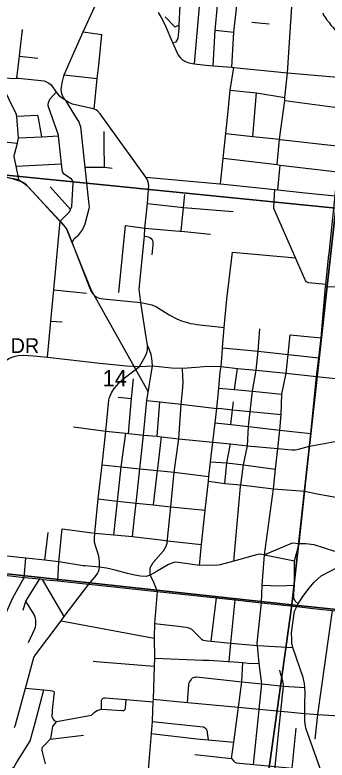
# Model space of a CAD drawing. Extents: x -8.2 to 38.5, y -0.1 to 21.9.
# Drawn here: x 6.953 to 7.75, y 15.475 to 17.376 of the extents above; entities that cross this region are included whole.
import ezdxf

# ---------------------------------------------------------------- set-up
doc = ezdxf.new("R2010")
doc.units = 0
for name, color, linetype in [('GM_X_Adjacent_County_Text', 7, 'Continuous'), ('GM_X_Airport_Location_Class_3', 7, 'Continuous'), ('GM_X_County_Road_Text', 7, 'Continuous'), ('GM_X_Major_Lake', 7, 'Continuous'), ('GM_X_Minor_River', 7, 'Continuous'), ('GM_X_Township_Subdivision_Text', 7, 'Continuous'), ('GM_X_Township_Text', 7, 'Continuous'), ('GM_X_US_Location', 7, 'Continuous')]:
    doc.layers.add(name, color=color, linetype=linetype)

msp = doc.modelspace()

# ---------------------------------------------------------------- linework, layer by layer
at = {"layer": 'GM_X_Adjacent_County_Text'}
for points in [[(6.8589, 17.9964), (7.8777, 17.8803), (7.7722, 16.8835), (6.7536, 16.9855)], [(6.7536, 16.9855), (7.7722, 16.8835), (7.66, 15.8712), (6.65, 15.9814)], [(7.7722, 16.8835), (8.7794, 16.8117), (8.6736, 15.7659), (7.66, 15.8712)], [(7.66, 15.8712), (7.5202, 14.8634), (6.5306, 14.9717), (6.65, 15.9814)], [(7.66, 15.8712), (8.6736, 15.7659), (8.6117, 15.0774), (8.5928, 15.0619), (8.5723, 15.0415), (8.5525, 15.0184), (8.5405, 15.0046), (8.5226, 14.9831), (8.5094, 14.9667), (8.4937, 14.9454), (8.4864, 14.9373), (8.469, 14.9221), (8.4519, 14.9028), (8.4387, 14.8852), (8.4261, 14.8666), (8.4156, 14.8524), (8.4049, 14.847), (8.3954, 14.8305), (8.3869, 14.8201), (8.3765, 14.8112), (8.3645, 14.8016), (8.3536, 14.7875), (8.3469, 14.777), (7.5202, 14.8634)]]:
    msp.add_lwpolyline(points, close=True, dxfattribs=at)
at = {"layer": 'GM_X_Airport_Location_Class_3'}
msp.add_line((7.6679, 15.8566), (7.6718, 15.8654), dxfattribs=at)
for points in [[(7.6718, 15.8654), (7.6726, 15.8672), (7.6765, 15.8737), (7.6884, 15.8923), (7.7048, 15.9142), (7.717, 15.929), (7.7347, 15.9451), (7.7619, 15.959), (7.7744, 15.9656), (7.7953, 15.9816), (7.8059, 15.9913)], [(7.6628, 15.7625), (7.6606, 15.7735), (7.6599, 15.7828), (7.6597, 15.7997), (7.6672, 15.8548), (7.6679, 15.8566)], [(7.7413, 15.3282), (7.7488, 15.38), (7.7503, 15.3899), (7.749, 15.4031), (7.7461, 15.4159), (7.7314, 15.4563), (7.6959, 15.5563), (7.6932, 15.5748), (7.6932, 15.5939), (7.693, 15.6174), (7.6947, 15.648), (7.6938, 15.6606), (7.6922, 15.671), (7.6889, 15.6856), (7.6628, 15.7625)]]:
    msp.add_lwpolyline(points, dxfattribs=at)
at = {"layer": 'GM_X_Minor_River'}
msp.add_lwpolyline([(7.7395, 17.3818), (7.7413, 17.376), (7.746, 17.369), (7.7486, 17.3647), (7.7556, 17.3573), (7.7596, 17.3503), (7.7651, 17.3452), (7.7685, 17.341), (7.7743, 17.3324), (7.779, 17.3235), (7.78, 17.3193)], dxfattribs=at)
at = {"layer": 'GM_X_Township_Subdivision_Text'}
for p, q in [((7.4118, 17.2515), (7.4245, 17.3982)), ((7.5578, 17.3578), (7.6021, 17.354)), ((7.1279, 17.3332), (7.1755, 17.3266)), ((7.4644, 17.3371), (7.5122, 17.3324)), ((6.9648, 17.2708), (7.0116, 17.2657)), ((7.0794, 17.2237), (7.1636, 17.2141)), ((7.5611, 17.0665), (7.5702, 17.1774)), ((7.6426, 17.1581), (7.7987, 17.1368)), ((6.7638, 17.0677), (6.9596, 17.0492)), ((6.9563, 16.9902), (7.0723, 16.9961)), ((7.6242, 16.9301), (7.6305, 16.9934)), ((7.0956, 16.8798), (7.0431, 16.9377)), ((7.2186, 16.6683), (7.2354, 16.8388)), ((7.5085, 16.771), (7.67, 16.7563)), ((7.0526, 16.6751), (7.1359, 16.6664)), ((7.7463, 16.6839), (7.7732, 16.6831)), ((7.0448, 16.5955), (7.0742, 16.5938)), ((7.5135, 16.4207), (7.5213, 16.4747)), ((7.2169, 16.4009), (7.2514, 16.3977)), ((7.3165, 16.3013), (7.3235, 16.3894)), ((7.1026, 16.3255), (7.1853, 16.3144)), ((7.0742, 16.0653), (7.1571, 16.0546)), ((7.0298, 15.985), (7.0382, 16.0559)), ((7.5906, 15.9988), (7.6674, 15.9837)), ((7.0792, 15.8412), (7.024, 15.9364)), ((7.4544, 15.7783), (7.4679, 15.889)), ((7.0715, 15.8305), (7.3091, 15.7865)), ((7.236, 15.6075), (7.2372, 15.6298)), ((7.0599, 15.5734), (7.1485, 15.5901)), ((7.6609, 15.455), (7.6713, 15.5569)), ((7.0435, 15.5286), (7.1285, 15.5389))]:
    msp.add_line(p, q, dxfattribs=at)
for points in [[(7.6225, 16.9944), (7.6285, 17.059), (7.6426, 17.1581), (7.6428, 17.1655), (7.6492, 17.2288), (7.6623, 17.424), (7.664, 17.4416), (7.6611, 17.4592), (7.6556, 17.4742), (7.6502, 17.482), (7.6447, 17.489)], [(7.3554, 17.3064), (7.3653, 17.3077), (7.3697, 17.3166), (7.3724, 17.3418), (7.3728, 17.3502), (7.3763, 17.4185), (7.375, 17.4257), (7.3717, 17.4316), (7.3682, 17.4359), (7.3641, 17.4398), (7.3445, 17.4538)], [(7.5072, 17.2431), (7.5122, 17.3324), (7.5238, 17.4387)], [(7.4598, 17.2467), (7.4644, 17.3371), (7.4701, 17.4004)], [(7.3365, 17.3712), (7.3617, 17.3462), (7.3728, 17.3502)], [(6.9583, 17.2147), (6.9648, 17.2708), (6.9728, 17.3389)], [(7.156, 17.136), (7.1636, 17.2141), (7.1677, 17.2482), (7.1755, 17.3266)], [(7.4778, 16.9455), (7.4847, 17.0106), (7.4915, 17.0742), (7.4976, 17.1307), (7.5025, 17.1844), (7.5124, 17.2423)], [(6.7772, 17.1965), (6.8296, 17.2196), (6.8539, 17.2221), (6.9085, 17.2178), (6.9103, 17.2176), (6.9486, 17.2138), (6.9583, 17.2147), (6.9623, 17.215), (7.0281, 17.2079), (7.0373, 17.2043), (7.0404, 17.2021), (7.0458, 17.198), (7.0585, 17.1796), (7.0667, 17.1701), (7.0809, 17.1604)], [(6.9639, 16.9533), (6.9563, 16.9902), (6.9516, 17.0152), (6.9513, 17.0174), (6.9529, 17.0238), (6.9596, 17.0492), (6.9629, 17.0616), (6.9628, 17.0624), (6.9582, 17.1174), (6.9578, 17.1213), (6.957, 17.1239), (6.938, 17.1621), (6.9103, 17.2176)], [(7.0362, 16.5036), (7.0448, 16.5955), (7.0526, 16.6751), (7.0687, 16.8502), (7.0921, 16.8729), (7.0952, 16.8789), (7.0956, 16.8798), (7.0985, 16.8876), (7.1022, 16.9482), (7.1015, 16.9532), (7.0982, 16.9574), (7.0791, 16.9704), (7.0758, 16.9743), (7.0737, 16.9819), (7.0723, 16.9961), (7.0649, 17.0682), (7.0647, 17.0695), (7.0391, 17.1418), (7.0385, 17.1444), (7.0385, 17.1478), (7.0393, 17.1521), (7.0426, 17.1611), (7.0585, 17.1796)], [(7.5025, 17.1844), (7.5702, 17.1774), (7.6428, 17.1655)], [(7.0992, 16.7953), (7.1046, 16.8058), (7.1158, 16.8146), (7.1263, 16.8284), (7.1327, 16.8435), (7.1433, 16.8829), (7.1437, 16.8857), (7.1437, 16.8888), (7.1433, 16.8918), (7.1327, 16.9882), (7.1214, 17.091), (7.1185, 17.0997), (7.117, 17.1036), (7.1135, 17.1097), (7.0832, 17.1582)], [(7.0222, 17.0658), (7.0129, 17.1178), (7.0127, 17.1184), (7.012, 17.119), (7.0107, 17.1194), (6.9582, 17.1174)], [(7.1801, 17.0789), (7.1807, 17.0459), (7.1816, 16.9882)], [(7.4915, 17.0742), (7.5611, 17.0665), (7.6285, 17.059), (7.6305, 17.0588), (7.7825, 17.0418)], [(6.9628, 17.0624), (7.0222, 17.0658), (7.0649, 17.0682)], [(7.4847, 17.0106), (7.6225, 16.9944), (7.6305, 16.9934), (7.7766, 16.9762)], [(7.1327, 16.9882), (7.1698, 16.9884), (7.1816, 16.9882), (7.1831, 16.9881), (7.202, 16.9858)], [(7.7468, 16.6888), (7.7024, 16.6932), (7.6996, 16.6942), (7.6976, 16.6957), (7.6954, 16.6987), (7.6937, 16.7023), (7.67, 16.7563), (7.6145, 16.8826), (7.6139, 16.886), (7.6171, 16.9308)], [(7.3778, 16.8244), (7.384, 16.885), (7.3873, 16.9182)], [(7.2916, 16.8955), (7.384, 16.885), (7.5109, 16.875)], [(7.2354, 16.8388), (7.2854, 16.8324), (7.3737, 16.8248), (7.3778, 16.8244), (7.4527, 16.8167)], [(7.2839, 16.8118), (7.2898, 16.8108), (7.2938, 16.8099), (7.298, 16.8082), (7.3012, 16.8061), (7.3039, 16.8028), (7.3053, 16.799), (7.3058, 16.7949), (7.3051, 16.7895), (7.303, 16.764)], [(7.4872, 16.5786), (7.494, 16.6514), (7.5085, 16.771)], [(7.5126, 15.9832), (7.5295, 16.1731), (7.5301, 16.1771), (7.5372, 16.2284), (7.5475, 16.2771), (7.5496, 16.3267), (7.5538, 16.3642), (7.5596, 16.4161), (7.5693, 16.4697), (7.574, 16.5184), (7.5786, 16.5755)], [(7.2539, 16.0457), (7.259, 16.0939), (7.2628, 16.1307), (7.2721, 16.2185), (7.2818, 16.3046), (7.2904, 16.393), (7.3045, 16.4809), (7.3038, 16.4918), (7.3027, 16.5), (7.3009, 16.5104), (7.2982, 16.5194), (7.2921, 16.5335)], [(7.4835, 16.5269), (7.574, 16.5184), (7.613, 16.5142), (7.6509, 16.51), (7.7293, 16.5014)], [(7.3429, 16.0349), (7.3433, 16.0388), (7.3511, 16.1214), (7.3595, 16.2099), (7.3716, 16.2953), (7.3775, 16.3834), (7.3822, 16.4249), (7.3825, 16.4409), (7.3817, 16.453), (7.3809, 16.4748)], [(7.243, 16.3083), (7.2514, 16.3977), (7.2565, 16.448)], [(7.4736, 16.424), (7.5135, 16.4207), (7.5596, 16.4161), (7.6345, 16.4087)], [(7.2904, 16.393), (7.3235, 16.3894), (7.3775, 16.3834), (7.4684, 16.3721), (7.4736, 16.373), (7.5088, 16.369), (7.5538, 16.3642), (7.6331, 16.3569)], [(7.5044, 16.3312), (7.5088, 16.369), (7.5113, 16.3893)], [(7.4643, 16.3353), (7.5044, 16.3312), (7.5496, 16.3267), (7.6299, 16.3173), (7.7084, 16.3088)], [(7.206, 16.0498), (7.215, 16.1361), (7.225, 16.2236), (7.2361, 16.3091)], [(7.3069, 16.1261), (7.3177, 16.214), (7.3184, 16.2196), (7.3275, 16.3004)], [(7.4888, 16.1812), (7.494, 16.2335), (7.5041, 16.2819)], [(7.1757, 16.2287), (7.225, 16.2236), (7.2721, 16.2185)], [(7.2721, 16.2185), (7.3177, 16.214), (7.3595, 16.2099), (7.4486, 16.1985)], [(7.4529, 16.2361), (7.494, 16.2335), (7.5372, 16.2284), (7.6182, 16.2178)], [(7.4477, 16.1873), (7.4888, 16.1812), (7.5301, 16.1771), (7.6131, 16.1669), (7.6931, 16.161), (7.7251, 16.1549), (7.7488, 16.1499), (7.7722, 16.1461), (7.8703, 16.1164), (7.9115, 16.0891), (7.9191, 16.0839), (7.9294, 16.0789), (7.9474, 16.073), (7.9656, 16.0684), (7.9859, 16.0673), (7.996, 16.0662), (8.012, 16.0644), (8.0197, 16.0635), (8.048, 16.0596), (8.0494, 16.0595), (8.1227, 16.0521), (8.1856, 16.0457)], [(7.166, 16.1414), (7.215, 16.1361), (7.2628, 16.1307)], [(7.2628, 16.1307), (7.3069, 16.1261), (7.3511, 16.1214), (7.4392, 16.1125)], [(7.0626, 15.9327), (7.0659, 15.981), (7.0742, 16.0653)], [(7.2989, 15.9471), (7.2984, 15.9655), (7.3063, 15.9793), (7.3327, 16.0095), (7.3391, 16.0207), (7.3423, 16.0286), (7.3429, 16.0349)], [(6.8, 15.5008), (6.7852, 15.5189), (6.7836, 15.523), (6.7831, 15.5266), (6.785, 15.544), (6.7908, 15.5767), (6.7938, 15.5936), (6.7961, 15.6067), (6.798, 15.6113), (6.8006, 15.6159), (6.8205, 15.6454), (6.833, 15.6641), (6.8634, 15.7094), (6.8708, 15.7204), (6.8795, 15.7362), (6.9478, 15.8895), (6.9768, 15.9415), (6.9811, 15.9903)], [(6.9742, 15.858), (6.981, 15.8807), (7.0169, 15.9374)], [(7.5841, 15.9215), (7.627, 15.9202), (7.6667, 15.9216)], [(6.9877, 15.775), (7.0044, 15.8101), (7.006, 15.814), (7.0071, 15.8208), (7.0071, 15.8266), (7.0065, 15.8329), (7.0048, 15.8396), (7.0033, 15.8446), (7.0011, 15.8493), (6.981, 15.8807)], [(7.4999, 15.7266), (7.5046, 15.7739), (7.5156, 15.8838)], [(7.7197, 15.5285), (7.7269, 15.5916), (7.7638, 15.8573)], [(7.3101, 15.8237), (7.3706, 15.8168), (7.3907, 15.8145), (7.3938, 15.8136), (7.3971, 15.8123), (7.4039, 15.809), (7.4079, 15.8059), (7.4299, 15.7835), (7.432, 15.782), (7.4347, 15.781), (7.4391, 15.7801), (7.4453, 15.7791), (7.4544, 15.7783), (7.5046, 15.7739), (7.5722, 15.7679), (7.6628, 15.7625)], [(7.1529, 15.7273), (7.1611, 15.7266), (7.3088, 15.7149)], [(7.3095, 15.735), (7.4331, 15.7306), (7.4496, 15.73), (7.4976, 15.7267), (7.4999, 15.7266), (7.5352, 15.7239), (7.5496, 15.7228), (7.5769, 15.7219)], [(7.5065, 15.4792), (7.512, 15.5207), (7.5239, 15.61), (7.5326, 15.6751), (7.5352, 15.7239)], [(7.5961, 15.2604), (7.6173, 15.4591), (7.6323, 15.5997), (7.6391, 15.6638), (7.639, 15.6672), (7.6385, 15.6703), (7.6371, 15.6767), (7.6347, 15.6855), (7.6318, 15.6935), (7.6294, 15.7049)], [(7.4054, 15.6832), (7.4071, 15.6848), (7.4089, 15.6858), (7.413, 15.687), (7.4151, 15.6874), (7.4165, 15.6875), (7.5326, 15.6751), (7.5838, 15.6697), (7.6391, 15.6638), (7.6938, 15.6606)], [(7.3939, 15.6223), (7.3971, 15.6682), (7.3977, 15.6708), (7.399, 15.6737), (7.4029, 15.6804), (7.4054, 15.6832)], [(6.8517, 15.3702), (6.9413, 15.4489), (6.9483, 15.4553), (6.9513, 15.4583), (6.9582, 15.47), (6.9827, 15.5088), (6.9927, 15.5247), (7.0042, 15.567), (7.0276, 15.6541)], [(6.9804, 15.659), (7.0276, 15.6541), (7.043, 15.6529), (7.0488, 15.6523), (7.0526, 15.6503), (7.0539, 15.6469)], [(7.0539, 15.6469), (7.0519, 15.635), (7.0523, 15.6327), (7.0523, 15.6312), (7.0497, 15.6127), (7.048, 15.5865), (7.0485, 15.5847), (7.0505, 15.5808), (7.0539, 15.5765), (7.0599, 15.5734), (7.0498, 15.5626), (7.049, 15.5607), (7.0464, 15.546), (7.0442, 15.5297), (7.0435, 15.5286), (7.0325, 15.5167), (7.0257, 15.5102), (7.0229, 15.5074), (7.022, 15.5053), (7.0218, 15.5037), (7.0218, 15.5009), (7.0241, 15.4926), (7.0303, 15.4659)], [(7.1746, 15.6054), (7.1743, 15.6274), (7.1745, 15.6284), (7.1754, 15.6299), (7.1767, 15.6312), (7.1789, 15.6329), (7.1815, 15.634), (7.1835, 15.6344)], [(7.1835, 15.6344), (7.2372, 15.6298), (7.3056, 15.6239)], [(7.3059, 15.6307), (7.3939, 15.6223), (7.5239, 15.61), (7.5768, 15.6049), (7.6323, 15.5997), (7.6932, 15.5939), (7.7269, 15.5916), (7.8218, 15.5853), (7.8423, 15.584), (7.8476, 15.5836), (7.8707, 15.582), (7.8845, 15.5808), (7.9496, 15.5749), (7.9745, 15.5726), (7.9982, 15.5704), (8.0296, 15.5676), (8.0501, 15.5657)], [(7.1485, 15.5901), (7.1507, 15.5914), (7.1528, 15.594), (7.156, 15.597), (7.1587, 15.5991), (7.1635, 15.6019), (7.1682, 15.6039), (7.1713, 15.6047), (7.1746, 15.6054), (7.2275, 15.6016), (7.2304, 15.6022), (7.2328, 15.6031), (7.235, 15.6047), (7.236, 15.6075)], [(7.3038, 15.574), (7.4339, 15.56), (7.4367, 15.559), (7.4388, 15.5577), (7.4403, 15.5562), (7.4414, 15.5546), (7.4427, 15.5525), (7.4436, 15.5507), (7.4439, 15.549), (7.4444, 15.5452), (7.4467, 15.5269)], [(7.3013, 15.5429), (7.4181, 15.5297), (7.4467, 15.5269), (7.512, 15.5207)], [(7.4127, 15.4899), (7.5065, 15.4792), (7.512, 15.4726), (7.5149, 15.4702), (7.517, 15.4689), (7.5184, 15.4683), (7.5628, 15.4642), (7.6173, 15.4591), (7.6609, 15.455)]]:
    msp.add_lwpolyline(points, dxfattribs=at)
at = {"layer": 'GM_X_Township_Text'}
for p, q in [((7.6563, 16.5604), (7.7348, 16.5524)), ((7.2711, 16.4793), (7.3045, 16.4809))]:
    msp.add_line(p, q, dxfattribs=at)
for points in [[(7.2921, 16.5335), (7.2884, 16.5541), (7.2748, 16.6426), (7.2709, 16.6767), (7.2839, 16.8118), (7.2854, 16.8324), (7.2916, 16.8955), (7.2946, 16.9309), (7.2952, 16.9402), (7.2944, 16.9465), (7.2919, 16.9555), (7.288, 16.9626), (7.1709, 17.124), (7.164, 17.1313), (7.1603, 17.1339), (7.156, 17.136), (7.1499, 17.138), (7.1001, 17.149), (7.0897, 17.1535), (7.0832, 17.1582), (7.0809, 17.1604), (7.0758, 17.1686), (7.0728, 17.1762), (7.0713, 17.1849), (7.072, 17.1931), (7.0746, 17.2066), (7.0794, 17.2237), (7.0881, 17.2445), (7.1006, 17.2718), (7.1279, 17.3332), (7.157, 17.3976)], [(7.3194, 17.3827), (7.3269, 17.3696), (7.336, 17.3521), (7.3554, 17.3064), (7.3702, 17.2735), (7.3749, 17.2678), (7.3812, 17.2619), (7.3888, 17.2573), (7.397, 17.2538), (7.4118, 17.2515), (7.4327, 17.2492), (7.4598, 17.2467), (7.5072, 17.2431), (7.5124, 17.2423)], [(7.5124, 17.2423), (7.6492, 17.2288), (7.8065, 17.2149), (7.8449, 17.2096), (7.9234, 17.1997), (8.0579, 17.1826), (8.1224, 17.1742), (8.1796, 17.1668), (8.1975, 17.1636), (8.2072, 17.159), (8.2148, 17.1539), (8.2205, 17.1491), (8.2259, 17.1427), (8.2317, 17.1333), (8.237, 17.1223), (8.2468, 17.1037), (8.2531, 17.0963), (8.2667, 17.0853), (8.2822, 17.0786)], [(7.6765, 15.8737), (7.6685, 15.881), (7.6653, 15.8888), (7.665, 15.8995), (7.6667, 15.9216), (7.6674, 15.9837), (7.6793, 16.0269), (7.6931, 16.161), (7.7053, 16.2759), (7.7084, 16.3088), (7.7234, 16.4541), (7.7293, 16.5014), (7.7348, 16.5524), (7.7463, 16.6839), (7.7468, 16.6888), (7.7549, 16.7647), (7.7552, 16.7672), (7.7632, 16.8416), (7.7711, 16.9152), (7.7766, 16.9762), (7.7825, 17.0418), (7.7987, 17.1368), (7.8065, 17.2149)], [(6.7616, 17.0454), (6.7745, 17.0409), (6.7908, 17.0329), (6.8052, 17.0241), (6.8246, 17.0125), (6.8758, 16.9794), (6.8868, 16.974), (6.8957, 16.9714), (6.9064, 16.9696), (6.946, 16.9592), (6.9639, 16.9533)], [(7.288, 16.9626), (7.4765, 16.9456), (7.4778, 16.9455), (7.6171, 16.9308), (7.6242, 16.9301), (7.6946, 16.9226), (7.7711, 16.9152)], [(6.9639, 16.9533), (6.9713, 16.9503), (6.9777, 16.9467), (6.9843, 16.9403), (7.0687, 16.8502), (7.0816, 16.8349), (7.0857, 16.8291), (7.0885, 16.8226), (7.0992, 16.7953), (7.1438, 16.6809), (7.1484, 16.671), (7.1521, 16.6649), (7.1554, 16.6611), (7.1577, 16.6594)], [(7.1577, 16.6594), (7.1607, 16.657), (7.1687, 16.6536), (7.1785, 16.6519), (7.2748, 16.6426)], [(7.2748, 16.6426), (7.2911, 16.6396), (7.3026, 16.6366), (7.3149, 16.6314), (7.3475, 16.6111), (7.3665, 16.6009), (7.3789, 16.596), (7.3905, 16.5926), (7.4019, 16.5894), (7.4097, 16.588)], [(7.4097, 16.588), (7.4175, 16.5866), (7.4872, 16.5786)], [(7.48, 16.4794), (7.4821, 16.5118), (7.4835, 16.5269), (7.4872, 16.5786)], [(7.5628, 15.4642), (7.5767, 15.6038), (7.5768, 15.6049), (7.5838, 15.6697), (7.5769, 15.7219), (7.5722, 15.7679), (7.5717, 15.7733), (7.5831, 15.8765), (7.5841, 15.9215), (7.5906, 15.9988), (7.6131, 16.1669), (7.6182, 16.2178), (7.6249, 16.2702), (7.6299, 16.3173), (7.6331, 16.3569), (7.6345, 16.4087), (7.6456, 16.4623), (7.6509, 16.51), (7.6563, 16.5604)], [(7.2711, 16.4793), (7.2852, 16.5036), (7.2899, 16.5146), (7.2915, 16.5223), (7.2921, 16.5335)], [(6.7042, 16.4854), (6.8506, 16.4673), (6.8604, 16.4665), (6.8695, 16.4666), (6.8785, 16.4681), (6.8867, 16.4704), (6.8976, 16.4753), (6.9398, 16.5005), (6.9512, 16.5053), (6.962, 16.5074), (6.9752, 16.5082), (7.0012, 16.5067), (7.0362, 16.5036)], [(7.0362, 16.5036), (7.1698, 16.488), (7.2382, 16.4814), (7.2711, 16.4793)], [(7.169, 15.9678), (7.1695, 15.9827), (7.1673, 15.9954), (7.1631, 16.0092), (7.1589, 16.0222), (7.1569, 16.031), (7.1566, 16.0416), (7.1571, 16.0546), (7.166, 16.1414), (7.1757, 16.2287), (7.1853, 16.3144), (7.1933, 16.3933), (7.1949, 16.4005), (7.1974, 16.4063), (7.2, 16.4121), (7.2025, 16.4169), (7.2071, 16.4237), (7.2125, 16.4304), (7.219, 16.4373), (7.2278, 16.4459), (7.2356, 16.4521), (7.2711, 16.4793)], [(7.3045, 16.4809), (7.3528, 16.4758), (7.3809, 16.4748), (7.4158, 16.4776), (7.436, 16.4798), (7.4554, 16.4804), (7.48, 16.4794)], [(7.4249, 15.9718), (7.4298, 16.025), (7.4392, 16.1125), (7.4477, 16.1873), (7.4486, 16.1985), (7.4529, 16.2361), (7.4583, 16.2867), (7.4643, 16.3353), (7.4684, 16.3721), (7.4736, 16.424), (7.4777, 16.466), (7.48, 16.4794)], [(7.48, 16.4794), (7.5213, 16.4747), (7.5693, 16.4697), (7.6456, 16.4623), (7.7234, 16.4541), (7.8117, 16.4446), (7.8406, 16.436), (7.8792, 16.429), (7.946, 16.4217)], [(7.1853, 16.3144), (7.2361, 16.3091), (7.243, 16.3083), (7.2818, 16.3046), (7.3165, 16.3013), (7.3275, 16.3004), (7.3716, 16.2953), (7.4583, 16.2867), (7.5041, 16.2819), (7.5475, 16.2771), (7.6249, 16.2702), (7.6599, 16.2664), (7.6685, 16.2667), (7.6775, 16.2685), (7.7053, 16.2759), (7.7894, 16.2915), (7.8552, 16.2848), (7.8636, 16.2848), (7.8697, 16.2853), (7.8945, 16.2901), (7.9029, 16.2911), (7.9164, 16.2916), (7.9277, 16.2907)], [(7.1571, 16.0546), (7.206, 16.0498), (7.2539, 16.0457), (7.333, 16.0361)], [(7.7697, 16.0076), (7.7175, 16.0247), (7.6952, 16.0272), (7.6793, 16.0269), (7.6607, 16.029), (7.5906, 15.9988), (7.5766, 16.0003), (7.5606, 15.9964), (7.5126, 15.9832), (7.4771, 15.9734), (7.4717, 15.9728), (7.4249, 15.9718), (7.3638, 15.9803), (7.3588, 15.9792), (7.3451, 15.9746), (7.3124, 15.9551), (7.2989, 15.9471), (7.2887, 15.9439), (7.2739, 15.9444), (7.2599, 15.947), (7.241, 15.9516), (7.2094, 15.9596), (7.1876, 15.9647), (7.169, 15.9678)], [(7.333, 16.0361), (7.3429, 16.0349), (7.4298, 16.025)], [(7.1274, 15.9712), (7.0659, 15.981), (7.0298, 15.985), (6.9811, 15.9903), (6.8596, 16.0033), (6.7418, 16.014), (6.7028, 16.0182), (6.652, 16.0241)], [(7.169, 15.9678), (7.1315, 15.9706), (7.1274, 15.9712)], [(6.7374, 15.9679), (6.7871, 15.9628), (6.8494, 15.9561), (6.9768, 15.9415), (7.0169, 15.9374), (7.024, 15.9364), (7.0626, 15.9327), (7.1419, 15.9244)], [(7.1419, 15.9244), (7.1608, 15.9466), (7.1645, 15.9513), (7.167, 15.9566), (7.1685, 15.962), (7.169, 15.9678)], [(7.2989, 15.9471), (7.3068, 15.929), (7.3124, 15.9163), (7.3163, 15.9058), (7.3101, 15.8237), (7.3091, 15.7877), (7.3091, 15.7865), (7.3095, 15.735), (7.3088, 15.7149), (7.3059, 15.6307), (7.3056, 15.6239), (7.3039, 15.5753), (7.3038, 15.574), (7.3013, 15.5429), (7.2955, 15.4713), (7.2922, 15.4301), (7.2909, 15.4145), (7.2868, 15.3689), (7.2823, 15.3178), (7.2817, 15.3114), (7.2812, 15.3091), (7.2725, 15.2713)], [(6.952, 15.5584), (6.9546, 15.5648), (6.9804, 15.659), (7.0014, 15.7366), (7.0061, 15.7442), (7.0715, 15.8305), (7.0792, 15.8412), (7.1419, 15.9244)], [(7.1419, 15.9244), (7.3163, 15.9058), (7.4679, 15.889), (7.5156, 15.8838), (7.5831, 15.8765), (7.6726, 15.8672), (7.6736, 15.867)], [(7.6736, 15.867), (7.7147, 15.8624), (7.7638, 15.8573), (7.809, 15.8524), (7.8533, 15.8476), (7.8751, 15.8451), (7.9034, 15.842), (7.9113, 15.8411)]]:
    msp.add_lwpolyline(points, dxfattribs=at)
at = {"layer": 'GM_X_US_Location'}
msp.add_lwpolyline([(5.9662, 17.4064), (5.9857, 17.3408), (6.0536, 17.2676), (6.0656, 17.2593), (6.1316, 17.2472), (6.2364, 17.2318), (6.2749, 17.2142), (6.398, 17.1559), (6.4557, 17.1126), (6.7633, 17.0468), (6.8914, 16.9695), (6.9592, 16.9572), (6.9787, 16.9469), (7.0844, 16.832), (7.1474, 16.6761), (7.2926, 16.4169)], dxfattribs=at)

# ---------------------------------------------------------------- texts
at = {"layer": 'GM_X_County_Road_Text'}
msp.add_text('14', height=0.04186, rotation=0, dxfattribs=at).set_placement((7.1771, 16.4285))
at = {"layer": 'GM_X_Major_Lake'}
msp.add_text('DR', height=0.03788, rotation=0, dxfattribs=at).set_placement((6.9423, 16.5137))

doc.saveas('drawing.dxf')
